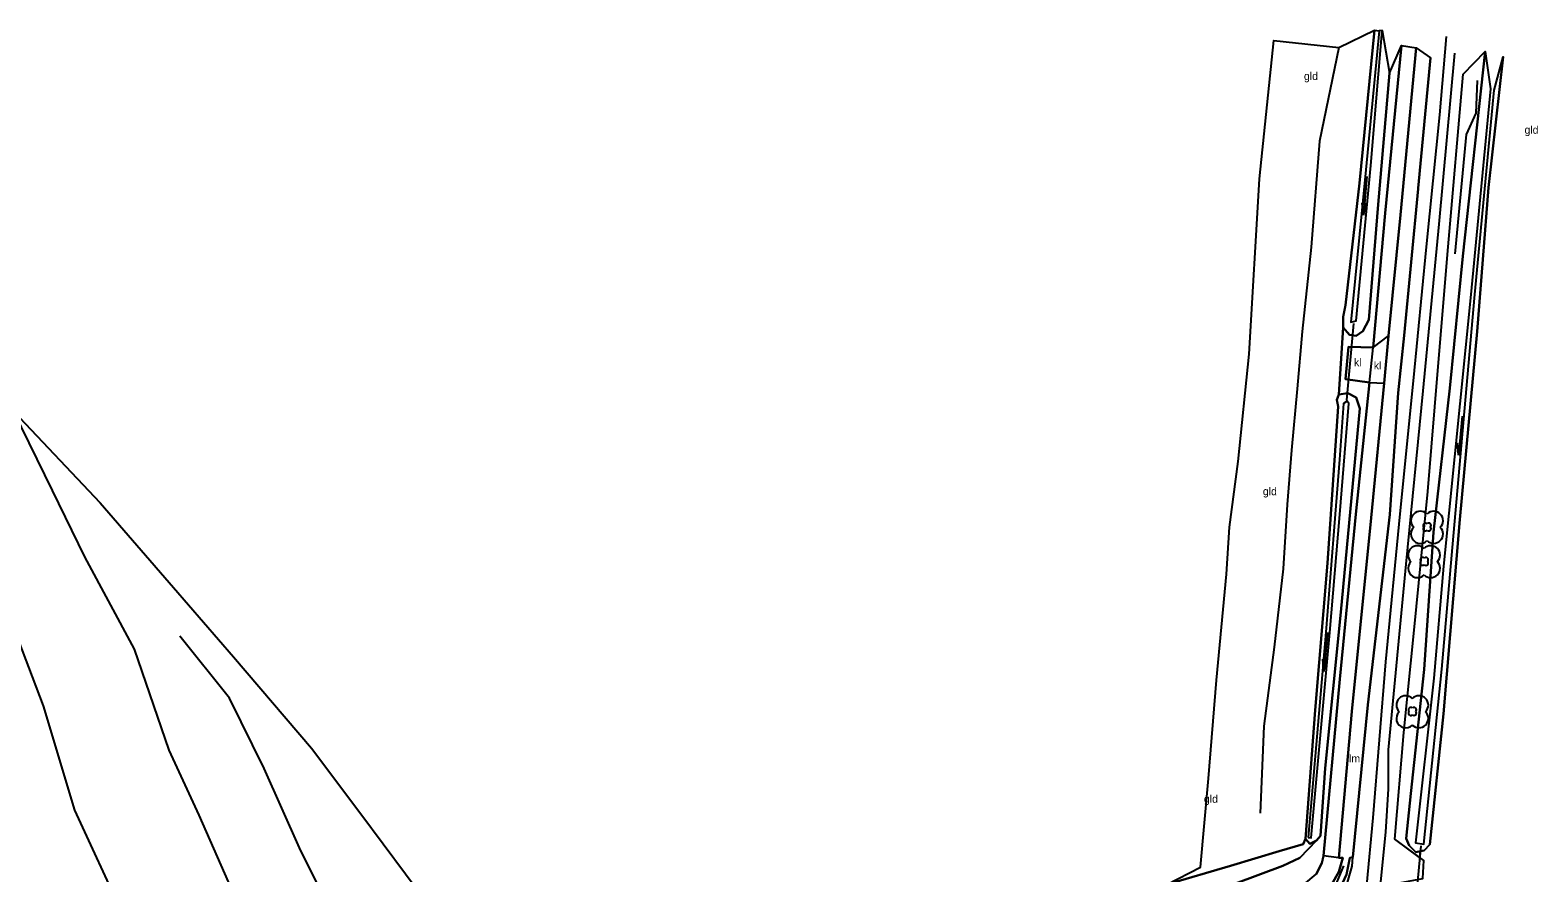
# Model space of a CAD drawing. Extents: x 154825 to 158680, y 370717 to 378075.
# Drawn here: x 156903 to 157095.8, y 374780.9 to 374888.7 of the extents above; entities that cross this region are included whole.
import ezdxf

# ---------------------------------------------------------------- set-up
doc = ezdxf.new("R2010")
doc.units = 0
for name, color, linetype in [('boom', 7, 'Continuous'), ('cultuurscheiding', 7, 'Continuous'), ('duiker lijn', 7, 'Continuous'), ('grasland_productiegrasl(vs)', 7, 'Continuous'), ('hoogteverschillijn', 7, 'Continuous'), ('insteek sloot', 7, 'Continuous'), ('klinkerverharding(vs)', 7, 'Continuous'), ('maaiveldlijn algemeen', 7, 'Continuous'), ('maaiveldlijn algemeen - bomenrij', 7, 'Continuous'), ('maaiveldlijn algemeen - gesloten verharding', 7, 'Continuous'), ('maaiveldlijn algemeen - onverhard', 7, 'Continuous'), ('maaiveldlijn algemeen - open verharding', 7, 'Continuous'), ('palenrij', 7, 'Continuous'), ('Sloot bodem', 7, 'Continuous'), ('stroomrichting  watergangen', 7, 'Continuous'), ('talud(boven)', 7, 'Continuous'), ('talud(onder)', 7, 'Continuous'), ('verlichtingsobject', 7, 'Continuous'), ('vlak_Bos', 7, 'Continuous'), ('vlak_Grasland', 7, 'Continuous'), ('vlak_Grazige_vegetatie', 7, 'Continuous')]:
    doc.layers.add(name, color=color, linetype=linetype)

msp = doc.modelspace()

# ---------------------------------------------------------------- linework, layer by layer
at = {"layer": 'boom'}
for centre, radius, start, end in [((157080.75, 374825.98), 1.2, 45, 225), ((157082.45, 374825.98), 1.2, 315, 135), ((157080.75, 374824.28), 1.2, 134.7431, 315), ((157081.4, 374825.38), 0.3, 45, 225), ((157081.4, 374824.96), 0.3, 134.7431, 315), ((157082.45, 374824.28), 1.2, 225, 45), ((157081.83, 374825.38), 0.3, 315, 135), ((157081.83, 374824.96), 0.3, 225, 45), ((157080.38, 374821.58), 1.2, 45, 225), ((157081.03, 374820.99), 0.3, 45, 225), ((157082.08, 374821.58), 1.2, 315, 135), ((157081.46, 374820.99), 0.3, 315, 135), ((157080.38, 374819.89), 1.2, 134.7431, 315), ((157081.03, 374820.56), 0.3, 134.7431, 315), ((157082.08, 374819.89), 1.2, 225, 45), ((157081.46, 374820.56), 0.3, 225, 45), ((157078.88, 374802.38), 1.2, 45, 225), ((157079.53, 374801.78), 0.3, 45, 225), ((157080.57, 374802.38), 1.2, 315, 135), ((157079.95, 374801.78), 0.3, 315, 135), ((157078.88, 374800.68), 1.2, 134.7431, 315), ((157079.53, 374801.36), 0.3, 134.7431, 315), ((157080.57, 374800.68), 1.2, 225, 45), ((157079.95, 374801.36), 0.3, 225, 45)]:
    msp.add_arc(centre, radius, start, end, dxfattribs=at)
at = {"layer": 'cultuurscheiding'}
msp.add_lwpolyline([(157070.87, 374850.7), (157070.34, 374842.13)], dxfattribs=at)
at = {"layer": 'duiker lijn'}
for points in [[(157071.37, 374841.41), (157072.26, 374851.22)], [(157080.79, 374784.38), (157080.24, 374778.46)]]:
    msp.add_lwpolyline(points, dxfattribs=at)
at = {"layer": 'hoogteverschillijn'}
for points in [[(157052.66, 374781.65), (157053.66, 374792.98), (157054.69, 374805.57), (157055.98, 374819.15), (157056.37, 374825.15), (157057.44, 374833.55), (157058.87, 374847.3), (157060.2, 374869.72), (157062.01, 374887.42), (157070.32, 374886.51), (157067.85, 374874.53), (157066.81, 374860.97), (157065.62, 374850.19), (157064.98, 374842.83), (157064.28, 374835.02), (157063.72, 374828.03), (157063.21, 374819.8), (157062.06, 374809.81), (157060.75, 374799.69), (157060.27, 374788.57)], [(156930.26, 374775.52), (156924.63, 374788.32), (156920.77, 374796.62), (156916.35, 374809.55), (156909.99, 374821.37), (156905.88, 374829.85), (156900.95, 374839.95), (156911.99, 374828.26), (156921.33, 374817.45), (156929.01, 374808.56), (156938.97, 374796.86), (156945.31, 374788.47), (156953.84, 374776.96)], [(156900.6, 374813.06), (156904.67, 374802.28), (156908.7, 374788.96), (156914.88, 374775.56)], [(156940.7, 374777.59), (156937.46, 374784.13), (156932.92, 374794.27), (156928.52, 374803.27), (156922.15, 374811.2)]]:
    msp.add_lwpolyline(points, dxfattribs=at)
at = {"layer": 'insteek sloot'}
for points in [[(157076.8, 374883.22), (157075.34, 374866.45), (157074.15, 374851.66), (157073.39, 374850.22), (157072.56, 374849.63), (157071.71, 374849.74), (157070.87, 374850.7), (157070.89, 374852.08), (157071.16, 374853.56), (157072.99, 374869.18), (157074.87, 374888.75)], [(157089.04, 374886.01), (157086.19, 374859.81), (157084.5, 374842.93), (157082.44, 374824.49), (157081.23, 374806.92), (157079.52, 374791.08), (157078.93, 374785.33), (157079.3, 374784.4), (157080.16, 374783.57), (157081.25, 374783.77), (157081.96, 374784.56), (157083.7, 374801.27), (157085.8, 374826.15), (157088.03, 374850.18), (157089.47, 374868.61), (157091.34, 374885.32)], [(157066.08, 374785.29), (157066.62, 374784.64), (157067.46, 374785.06), (157067.98, 374785.66), (157068.58, 374794.32), (157070.59, 374814.29), (157073.03, 374840.34), (157072.55, 374841.73), (157071.47, 374842.31), (157070.34, 374842.13), (157070.09, 374841.45), (157070.23, 374840.58), (157068.87, 374820.55), (157067.29, 374801.73), (157066.08, 374785.29)]]:
    msp.add_lwpolyline(points, dxfattribs=at)
at = {"layer": 'maaiveldlijn algemeen'}
msp.add_lwpolyline([(157065.36, 374667.38), (157065.27, 374667.72), (157065.42, 374684.69), (157066.13, 374700.3), (157067.61, 374717.18), (157069.63, 374736.89), (157071.42, 374755.28), (157073.09, 374770.71), (157074.7, 374787.98), (157076.34, 374807.93), (157078.17, 374826.85), (157079.86, 374843.87), (157081.55, 374861.03), (157083.22, 374877.93), (157084.11, 374887.93)], dxfattribs=at)
at = {"layer": 'maaiveldlijn algemeen - bomenrij'}
msp.add_lwpolyline([(157088.02, 374882.3), (157087.84, 374878.11), (157086.62, 374875.38), (157085.14, 374860.14)], dxfattribs=at)
at = {"layer": 'maaiveldlijn algemeen - gesloten verharding'}
for points in [[(157074.7, 374848.16), (157076.25, 374865.32), (157078.33, 374886.76), (157080.21, 374886.47), (157078.22, 374865.13), (157076.68, 374849.63)], [(157072.13, 374782.91), (157074.04, 374802.42), (157076.84, 374826.79), (157077.93, 374842.32), (157078.7, 374849.67), (157080.46, 374868.46), (157080.49, 374868.54), (157082.05, 374885.2)], [(157085.12, 374885.8), (157083.11, 374863.9), (157081.06, 374842.59), (157078.9, 374820.41), (157076.62, 374796.68), (157076.64, 374791.67), (157076.3, 374786.14), (157074.69, 374769.95)], [(157074.25, 374843.66), (157074.7, 374848.16)], [(157076.68, 374849.63), (157076.11, 374843.56)], [(157068.36, 374783.1), (157070.44, 374805.7), (157072.52, 374826.8), (157074.25, 374843.66)], [(157076.11, 374843.56), (157074.48, 374826.33), (157072.01, 374801.58), (157070.34, 374782.86)], [(157060.75, 374772.01), (157063.19, 374772.18), (157065.66, 374773.25), (157068.1, 374775.05), (157069.79, 374776.95), (157071.33, 374779.38), (157072.02, 374781.76), (157072.13, 374782.91)], [(157070.34, 374782.86), (157068.36, 374783.1)]]:
    msp.add_lwpolyline(points, dxfattribs=at)
at = {"layer": 'maaiveldlijn algemeen - onverhard'}
msp.add_lwpolyline([(157083.58, 374576.96), (157076.06, 374608.4), (157072.88, 374622.09), (157071.04, 374632.91), (157068.79, 374649.78), (157068.18, 374657.2), (157067.72, 374672.26), (157068.03, 374687.12), (157068.93, 374701.86), (157070.45, 374719.51), (157071.94, 374735.96), (157073.65, 374750.68), (157075.15, 374767.55), (157075.81, 374773.83), (157076.93, 374779.44), (157081.05, 374780.18), (157081.18, 374782.48), (157077.5, 374785.23), (157078.64, 374798.87), (157079.94, 374811.96), (157081.69, 374829.71), (157083.08, 374846.22), (157084.32, 374861.01), (157086.22, 374883.11)], dxfattribs=at)
at = {"layer": 'maaiveldlijn algemeen - open verharding'}
for points in [[(157074.25, 374843.66), (157071.18, 374844.09), (157071.58, 374848.21), (157074.7, 374848.16)], [(157074.7, 374848.16), (157076.68, 374849.63)], [(157074.25, 374843.66), (157076.11, 374843.56)], [(157054.73, 374776), (157057.79, 374776.48), (157060.63, 374777.26), (157063.26, 374778.19), (157065.86, 374779.45), (157067.45, 374780.77), (157068.16, 374782.15), (157068.36, 374783.1)], [(157070.34, 374782.86), (157070.84, 374782.85), (157070.33, 374781.04), (157069.44, 374779.49), (157067.48, 374777.82), (157065.11, 374776.55), (157062.64, 374775.57), (157060.63, 374774.88), (157060.73, 374772.43), (157060.75, 374772.01)], [(157072.13, 374782.91), (157071.73, 374782.86), (157071.32, 374780.69), (157070.33, 374778.56), (157068.76, 374776.37), (157067.1, 374774.66), (157065.06, 374773.45), (157062.71, 374772.67), (157060.73, 374772.43), (157062.71, 374772.67), (157065.06, 374773.45), (157067.1, 374774.66), (157068.76, 374776.37), (157070.33, 374778.56), (157071.32, 374780.69), (157071.73, 374782.86), (157072.1, 374782.91)]]:
    msp.add_lwpolyline(points, dxfattribs=at)
at = {"layer": 'palenrij'}
msp.add_lwpolyline([(157062.07, 374773.11), (157063.99, 374773.77), (157067.08, 374775.93), (157068.34, 374777.04), (157069.91, 374779.24), (157070.96, 374781.8)], dxfattribs=at)
at = {"layer": 'Sloot bodem'}
for points in [[(157075.87, 374888.7), (157075.5, 374888.66), (157073.8, 374870.87), (157071.88, 374851.4), (157072.55, 374851.53), (157074.4, 374871.44), (157075.87, 374888.7)], [(157089.71, 374881.22), (157087.21, 374854.9), (157083.69, 374820.16), (157082.48, 374805.82), (157080.12, 374784.74), (157081.21, 374784.57), (157083.48, 374806.98), (157084.99, 374824.02), (157087.73, 374854.94), (157090.2, 374881.05)], [(157066.39, 374785.46), (157066.78, 374785.41), (157069.16, 374811.69), (157070.45, 374826.79), (157071.61, 374840.96), (157071.38, 374841.29), (157070.94, 374840.97), (157070.4, 374833.8), (157068.66, 374811.71), (157066.39, 374785.46)]]:
    msp.add_lwpolyline(points, dxfattribs=at)
at = {"layer": 'stroomrichting  watergangen'}
for p, q in [((157073.92, 374870.02), (157073.46, 374865.05)), ((157073.46, 374865.05), (157073.33, 374866.62)), ((157073.48, 374865.06), (157073.89, 374866.59)), ((157086.08, 374839.34), (157085.62, 374834.37)), ((157085.62, 374834.37), (157085.49, 374835.94)), ((157085.63, 374834.38), (157086.05, 374835.91)), ((157068.87, 374811.67), (157068.41, 374806.7)), ((157068.41, 374806.7), (157068.28, 374808.27)), ((157068.43, 374806.71), (157068.85, 374808.23))]:
    msp.add_line(p, q, dxfattribs=at)
at = {"layer": 'talud(boven)'}
msp.add_lwpolyline([(157067.46, 374785.06), (157065.34, 374782.84), (157063.18, 374781.81), (157057.11, 374779.57), (157050.45, 374777.84), (157044.98, 374776.46), (157038.19, 374773.59), (157032.11, 374770.58), (157025.08, 374766.4), (157006.33, 374754.12), (156986.16, 374740.9), (156967.67, 374728.9), (156953.01, 374718.51), (156934.16, 374705.45), (156924.22, 374699.42), (156917.21, 374694.35), (156911.58, 374690.58), (156906.95, 374687.99), (156904.02, 374686.19), (156903.23, 374684.89)], dxfattribs=at)
at = {"layer": 'talud(onder)'}
msp.add_lwpolyline([(157066.08, 374785.29), (157065.76, 374784.59), (157062.71, 374783.71), (157056.46, 374781.82), (157048.33, 374779.45), (157042.28, 374777.13), (157036.32, 374774.56), (157027.45, 374769.57), (157015.6, 374762.27), (156994.36, 374748.1), (156977.05, 374736.39), (156960.33, 374725.15), (156934.34, 374707.46), (156912.59, 374692.79), (156904.49, 374687.16), (156900.93, 374686.12), (156896.33, 374689.54)], dxfattribs=at)
at = {"layer": 'vlak_Bos'}
msp.add_lwpolyline([(157048.33, 374779.45), (157056.46, 374781.82), (157062.71, 374783.71), (157065.76, 374784.59), (157066.08, 374785.29), (157066.62, 374784.64), (157067.46, 374785.06), (157065.34, 374782.84), (157063.18, 374781.81), (157057.11, 374779.57)], dxfattribs=at)
at = {"layer": 'vlak_Grasland'}
msp.add_lwpolyline([(157074.87, 374888.75), (157072.99, 374869.18), (157071.16, 374853.56), (157070.89, 374852.08), (157070.87, 374850.7), (157070.34, 374842.13), (157070.09, 374841.45), (157070.23, 374840.58), (157068.87, 374820.55), (157067.29, 374801.73), (157066.08, 374785.29), (157065.76, 374784.59), (157062.71, 374783.71), (157056.46, 374781.82), (157048.33, 374779.45), (157052.66, 374781.65), (157053.66, 374792.98), (157054.69, 374805.57), (157055.98, 374819.15), (157056.37, 374825.15), (157057.44, 374833.55), (157058.87, 374847.3), (157060.2, 374869.72), (157062.01, 374887.42), (157070.32, 374886.51)], close=True, dxfattribs=at)
msp.add_lwpolyline([(156900.95, 374839.95), (156911.99, 374828.26), (156921.33, 374817.45), (156929.01, 374808.56), (156938.97, 374796.86), (156945.31, 374788.47), (156953.84, 374776.96), (156958.57, 374770.63), (156965.3, 374760.56), (156970.86, 374751.49), (156976.52, 374742.17), (156994.36, 374748.1), (156977.05, 374736.39), (156960.33, 374725.15), (156934.34, 374707.46), (156912.59, 374692.79), (156904.49, 374687.16), (156900.93, 374686.12)], dxfattribs=at)
at = {"layer": 'vlak_Grazige_vegetatie'}
for points in [[(157073.8, 374870.87), (157071.88, 374851.4), (157072.55, 374851.53), (157074.4, 374871.44), (157075.87, 374888.7), (157076.8, 374883.22), (157075.34, 374866.45), (157074.15, 374851.66), (157073.39, 374850.22), (157072.56, 374849.63), (157071.71, 374849.74), (157070.87, 374850.7), (157070.89, 374852.08), (157071.16, 374853.56), (157072.99, 374869.18), (157074.87, 374888.75), (157075.5, 374888.66)], [(157079.3, 374784.4), (157080.16, 374783.57), (157080.72, 374783.68), (157080.65, 374782.87), (157077.5, 374785.23), (157078.64, 374798.87), (157079.94, 374811.96), (157081.69, 374829.71), (157083.08, 374846.22), (157084.32, 374861.01), (157086.22, 374883.11), (157089.04, 374886.01), (157086.19, 374859.81), (157084.5, 374842.93), (157082.44, 374824.49), (157081.23, 374806.92), (157079.52, 374791.08), (157078.93, 374785.33)], [(157080.12, 374784.74), (157081.21, 374784.57), (157083.48, 374806.98), (157084.99, 374824.02), (157087.73, 374854.94), (157090.2, 374881.05), (157091.34, 374885.32), (157089.47, 374868.61), (157088.03, 374850.18), (157085.8, 374826.15), (157083.7, 374801.27), (157081.96, 374784.56), (157081.25, 374783.77), (157080.72, 374783.68), (157080.16, 374783.57), (157079.3, 374784.4), (157078.93, 374785.33), (157079.52, 374791.08), (157081.23, 374806.92), (157082.44, 374824.49), (157084.5, 374842.93), (157086.19, 374859.81), (157089.04, 374886.01), (157089.71, 374881.22), (157087.21, 374854.9), (157083.69, 374820.16), (157082.48, 374805.82)], [(157072.55, 374841.73), (157073.03, 374840.34), (157070.59, 374814.29), (157068.58, 374794.32), (157067.98, 374785.66), (157067.46, 374785.06), (157066.62, 374784.64), (157066.08, 374785.29), (157067.29, 374801.73), (157068.87, 374820.55), (157070.23, 374840.58), (157070.09, 374841.45), (157070.34, 374842.13), (157071.47, 374842.31)], [(157066.39, 374785.46), (157066.78, 374785.41), (157069.16, 374811.69), (157070.45, 374826.79), (157071.61, 374840.96), (157071.38, 374841.29), (157070.94, 374840.97), (157070.4, 374833.8), (157068.66, 374811.71)]]:
    msp.add_lwpolyline(points, close=True, dxfattribs=at)
for points in [[(157057.11, 374779.57), (157063.18, 374781.81), (157065.34, 374782.84), (157067.46, 374785.06), (157067.98, 374785.66), (157068.58, 374794.32), (157070.59, 374814.29), (157073.03, 374840.34), (157072.55, 374841.73), (157071.47, 374842.31), (157070.34, 374842.13), (157070.87, 374850.7), (157071.71, 374849.74), (157072.56, 374849.63), (157073.39, 374850.22), (157074.15, 374851.66), (157075.34, 374866.45), (157076.8, 374883.22), (157078.33, 374886.76), (157076.25, 374865.32), (157074.7, 374848.16), (157071.58, 374848.21), (157071.18, 374844.09), (157074.25, 374843.66), (157072.52, 374826.8), (157070.44, 374805.7), (157068.36, 374783.1), (157068.16, 374782.15), (157067.45, 374780.77)], [(157069.44, 374779.49), (157070.33, 374781.04), (157070.84, 374782.85), (157070.34, 374782.86), (157072.01, 374801.58), (157074.48, 374826.33), (157076.11, 374843.56), (157076.68, 374849.63), (157078.22, 374865.13), (157080.21, 374886.47), (157082.05, 374885.2), (157080.49, 374868.54), (157080.46, 374868.46), (157078.7, 374849.67), (157077.93, 374842.32), (157076.84, 374826.79), (157074.04, 374802.42), (157072.13, 374782.91), (157071.73, 374782.86), (157071.32, 374780.69)]]:
    msp.add_lwpolyline(points, dxfattribs=at)

# ---------------------------------------------------------------- texts
at = {"layer": 'grasland_productiegrasl(vs)'}
for p in [(157065.87, 374882.37), (157094.07, 374875.49), (157060.62, 374829.24), (157053.08, 374789.89)]:
    msp.add_text('gld', height=1, dxfattribs=at).set_placement(p)
at = {"layer": 'klinkerverharding(vs)'}
for p in [(157072.26, 374845.75), (157074.8, 374845.33)]:
    msp.add_text('kl', height=1, dxfattribs=at).set_placement(p)
at = {"layer": 'verlichtingsobject'}
msp.add_text('lm', height=1, dxfattribs=at).set_placement((157071.64, 374795.05))

doc.saveas('drawing.dxf')
